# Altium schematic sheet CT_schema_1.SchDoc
size 628 x 258 mm
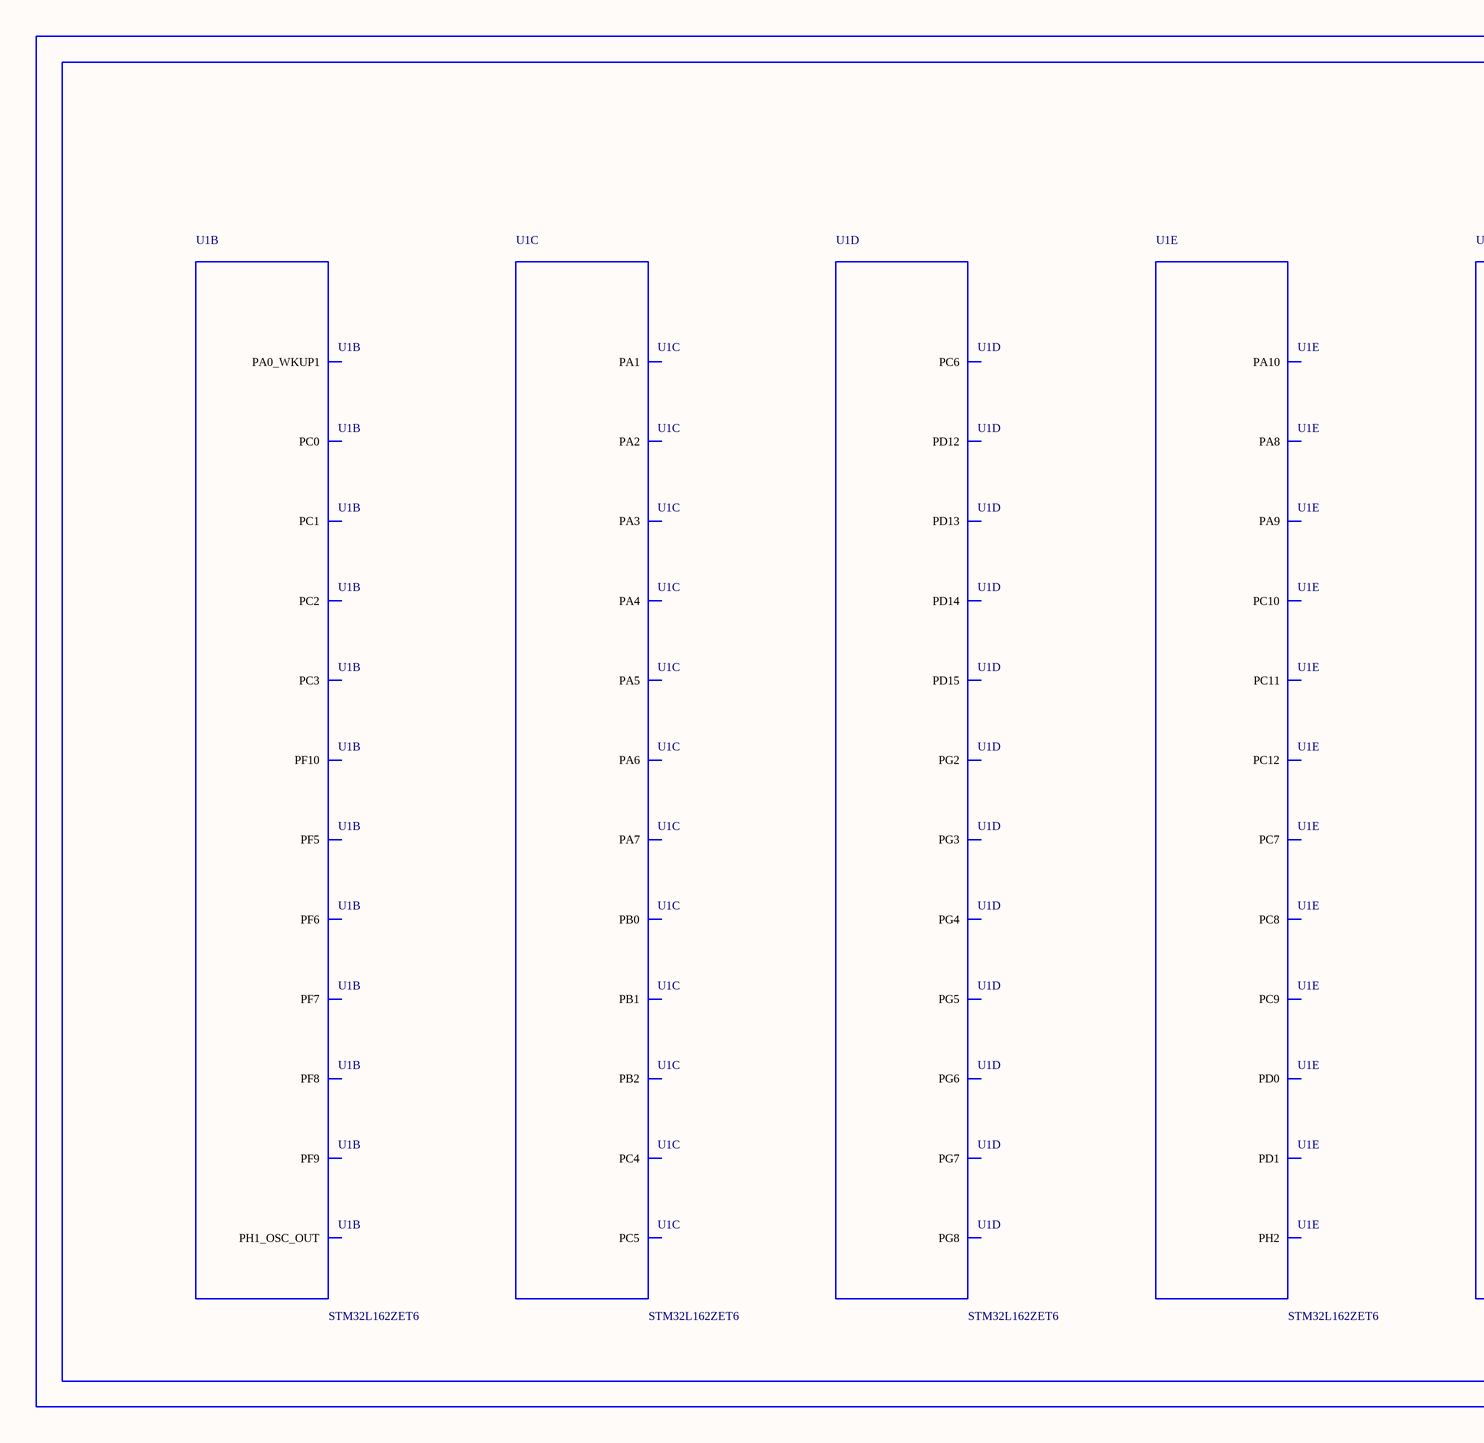
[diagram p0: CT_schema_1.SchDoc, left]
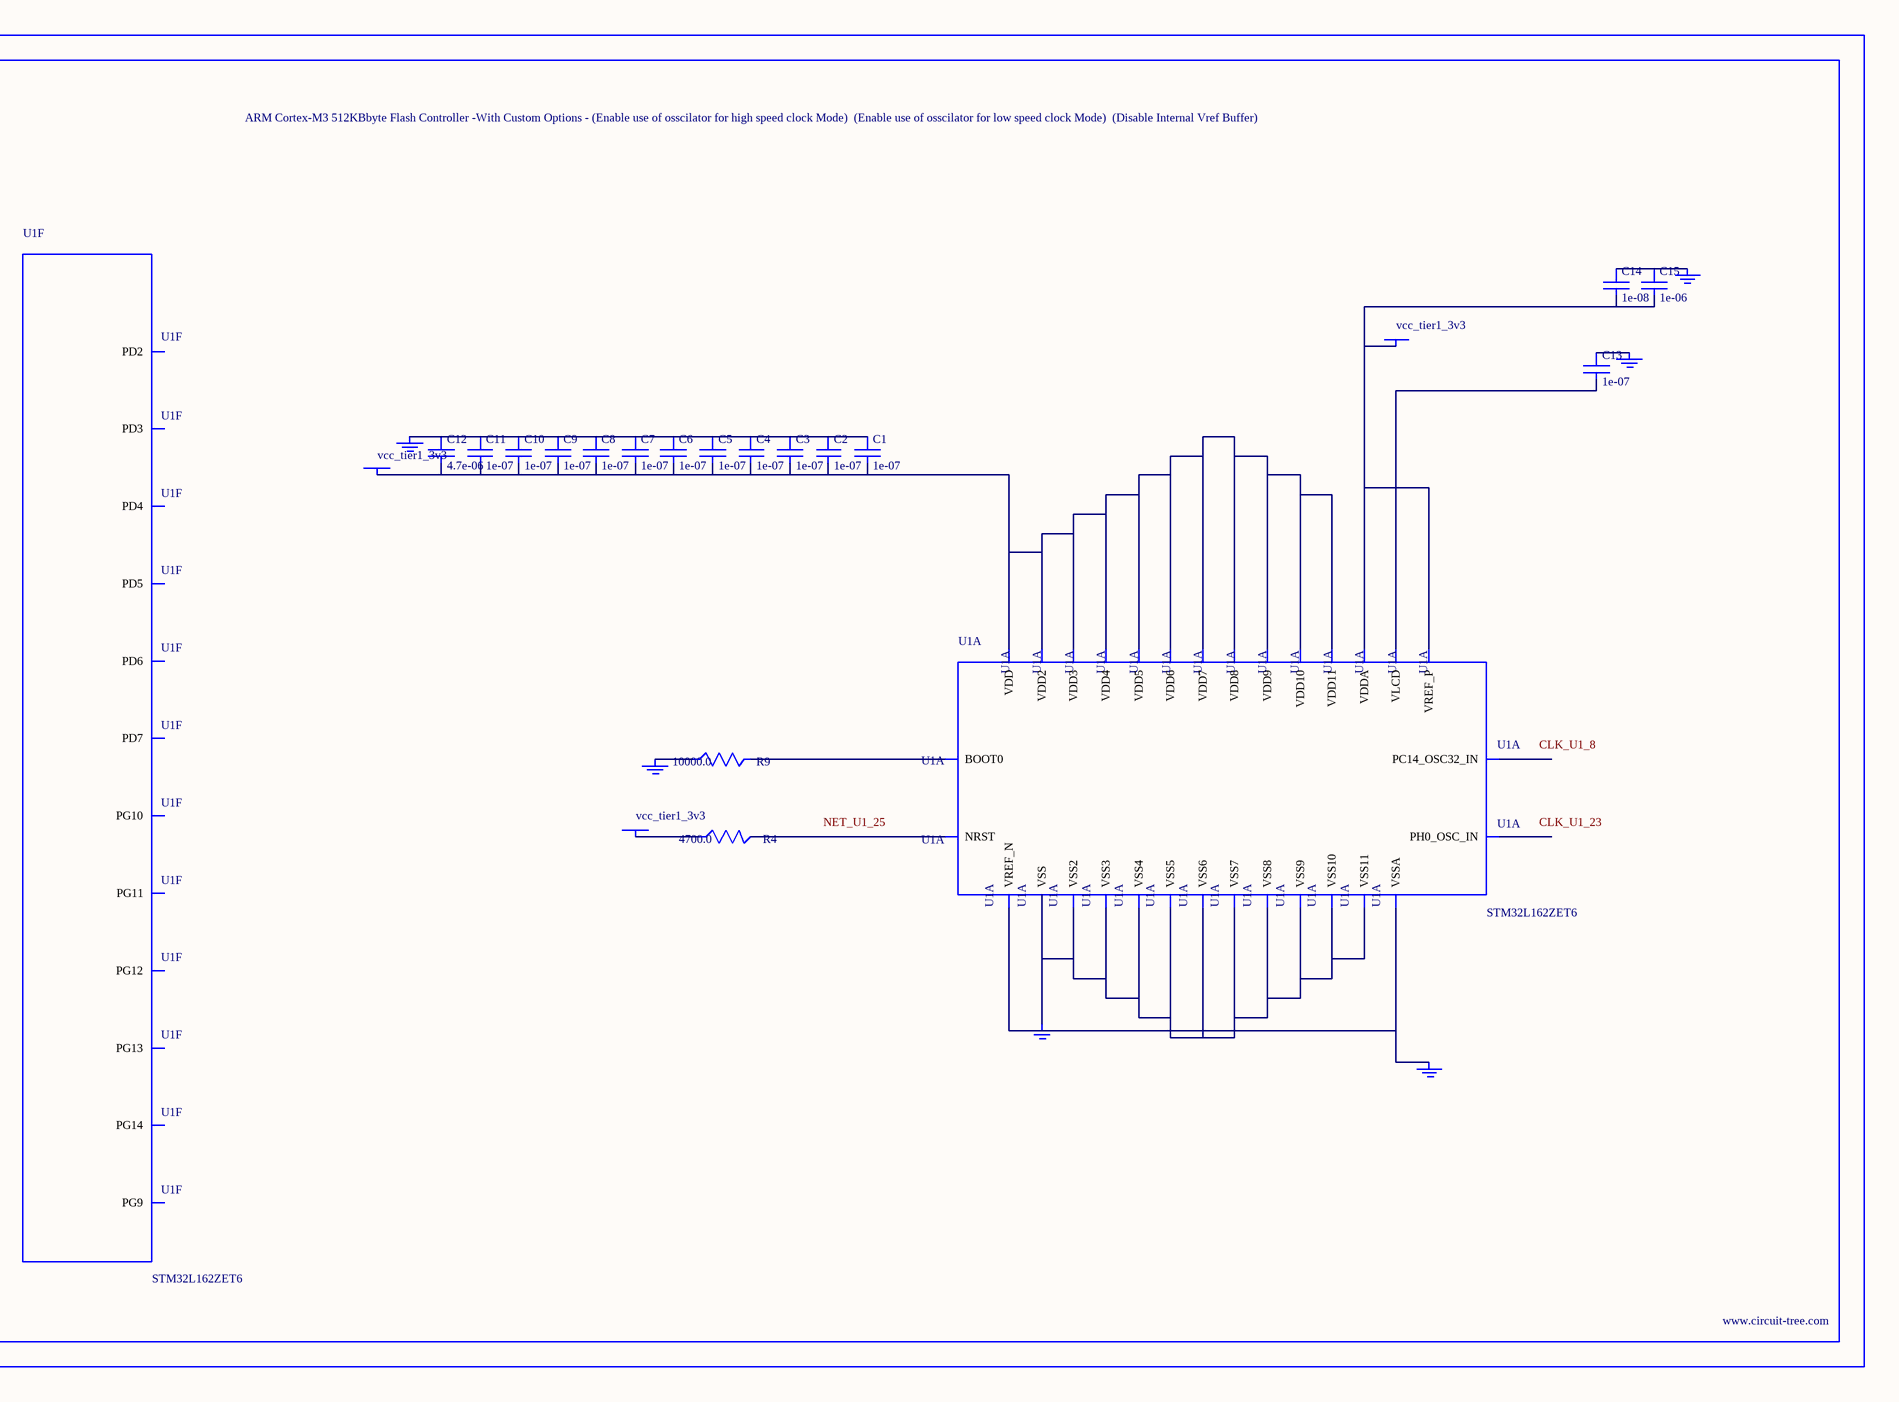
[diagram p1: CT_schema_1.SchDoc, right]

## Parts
BORDER0  (no value)
C1  1e-07  [C0603]
C2  1e-07  [C0603]
C3  1e-07  [C0603]
C4  1e-07  [C0603]
C5  1e-07  [C0603]
C6  1e-07  [C0603]
C7  1e-07  [C0603]
C8  1e-07  [C0603]
C9  1e-07  [C0603]
C10  1e-07  [C0603]
C11  1e-07  [C0603]
C12  4.7e-06  [C0603]
C13  1e-07  [C0603]
C14  1e-08  [C0603]
C15  1e-06  [C0603]
GND_INSTANCE_0_0  (no value)
GND_INSTANCE_0_1  (no value)
GND_INSTANCE_0_2  (no value)
GND_INSTANCE_0_3  (no value)
GND_INSTANCE_0_4  (no value)
GND_INSTANCE_0_5  (no value)
POWER_INSTANCE_0_0  vcc_tier1_3v3
POWER_INSTANCE_0_1  vcc_tier1_3v3
POWER_INSTANCE_0_2  vcc_tier1_3v3
R4  4700.0  [R0603]
R9  10000.0  [R0603]
U1  STM32L162ZET6  [LQFP144]  (parts A,B,C,D,E,F of 13)

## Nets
NetC1_1: C1.1 C2.1 C3.1 C4.1 C5.1 C6.1 C7.1 C8.1 C9.1 C10.1 C11.1 C12.1 GND_INSTANCE_0_1.0(GND)
NetC1_2: C1.2 C2.2 C3.2 C4.2 C5.2 C6.2 C7.2 C8.2 C9.2 C10.2 C11.2 C12.2 POWER_INSTANCE_0_0.0(PWR) U1.17(VDD) U1.39(VDD2) U1.52(VDD3) U1.62(VDD4) U1.72(VDD5) U1.84(VDD6) U1.95(VDD7) U1.108(VDD8) U1.121(VDD9) U1.131(VDD10) U1.144(VDD11)
NetC13_1: C13.1 GND_INSTANCE_0_0.0(GND)
NetC13_2: C13.2 U1.6(VLCD)
NetC14_1: C14.1 C15.1 GND_INSTANCE_0_3.0(GND)
NetC14_2: C14.2 C15.2 POWER_INSTANCE_0_1.0(PWR) U1.32(VREF_P) U1.33(VDDA)
NetGND_INSTANCE_0_2_0: GND_INSTANCE_0_2.0(GND) U1.30(VSSA) U1.31(VREF_N)
NetGND_INSTANCE_0_4_0: GND_INSTANCE_0_4.0(GND) R9.1
NetGND_INSTANCE_0_5_0: GND_INSTANCE_0_5.0(GND) U1.16(VSS) U1.38(VSS2) U1.51(VSS3) U1.61(VSS4) U1.71(VSS5) U1.83(VSS6) U1.94(VSS7) U1.107(VSS8) U1.120(VSS9) U1.130(VSS10) U1.143(VSS11)
NetPOWER_INSTANCE_0_2_0: POWER_INSTANCE_0_2.0(PWR) R4.1
NetR4_2: R4.2 U1.25(NRST)
NetR9_2: R9.2 U1.138(BOOT0)

Not connected (* = marked no-connect by the designer): U1 8(PC14_OSC32_IN) 15(PF5) 18(PF6) 19(PF7) 20(PF8) 21(PF9) 22(PF10) 23(PH0_OSC_IN) 24(PH1_OSC_OUT) 26(PC0) 27(PC1) 28(PC2) 29(PC3) 34(PA0_WKUP1) 35(PA1) 36(PA2) 37(PA3) 40(PA4) 41(PA5) 42(PA6) 43(PA7) 44(PC4) 45(PC5) 46(PB0) 47(PB1) 48(PB2) 81(PD12) 82(PD13) 85(PD14) 86(PD15) 87(PG2) 88(PG3) 89(PG4) 90(PG5) 91(PG6) 92(PG7) 93(PG8) 96(PC6) 97(PC7) 98(PC8) 99(PC9) 100(PA8) 101(PA9) 102(PA10) 106(PH2) 111(PC10) 112(PC11) 113(PC12) 114(PD0) 115(PD1) 116(PD2) 117(PD3) 118(PD4) 119(PD5) 122(PD6) 123(PD7) 124(PG9) 125(PG10) 126(PG11) 127(PG12) 128(PG13) 129(PG14)

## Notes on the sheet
- Labels drawn without touching a wire or pin: CLK_U1_8, CLK_U1_23, NET_U1_25

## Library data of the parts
BORDER0 = BORDER_PAGE0
C1-C11 C13 = 06035C104K4Z2A
C12 = GRM188R6YA475KE15D
C14 = 06035C103K4Z2A
C15 = C0603C105K3RACTU
GND_INSTANCE_0_0-GND_INSTANCE_0_5 = GND
POWER_INSTANCE_0_0-POWER_INSTANCE_0_2 = PWR
R4 = RC0603JR-074K7L
R9 = RC0603JR-0710KL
